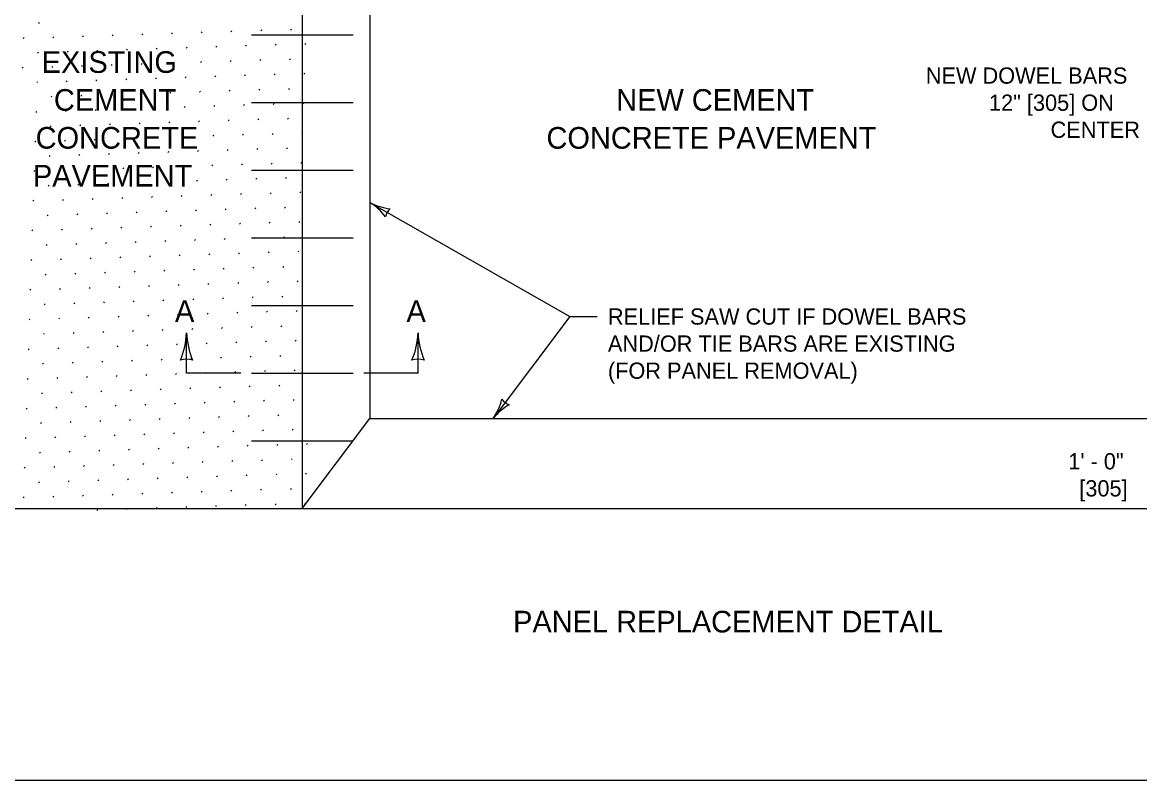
# Model space of a CAD drawing. Extents: x 49991.4 to 50021, y 49987.6 to 50011.4.
# Drawn here: x 50001.323 to 50005.45, y 49987.799 to 49990.601 of the extents above; entities that cross this region are included whole.
import ezdxf

# ---------------------------------------------------------------- set-up
doc = ezdxf.new("R2010")
doc.units = 0
for name, color, linetype in [('Level 1', 7, 'Continuous'), ('Level 10', 7, 'Continuous'), ('Level 2', 7, 'Continuous'), ('Level 3', 7, 'Continuous'), ('Level 4', 7, 'Continuous'), ('Level 6', 7, 'Continuous')]:
    doc.layers.add(name, color=color, linetype=linetype)

msp = doc.modelspace()

# ---------------------------------------------------------------- linework, layer by layer
at = {"layer": 'Level 1'}
for p, q in [((50002.3571, 49991.8039), (50002.3571, 49988.8039)), ((50002.6071, 49991.4706), (50002.6071, 49989.1372)), ((50002.3571, 49988.8039), (50002.6071, 49989.1372)), ((50002.6071, 49989.1372), (50005.8571, 49989.1372)), ((50001.1571, 49988.8039), (50002.3571, 49988.8039)), ((50002.3571, 49988.8039), (50006.1071, 49988.8039))]:
    msp.add_line(p, q, dxfattribs=at)
msp.add_lwpolyline([(49999.3835, 49998.9992), (50016.7501, 49998.9992), (50016.7501, 49987.7988), (49999.3835, 49987.7988)], close=True, dxfattribs=at)
at = {"layer": 'Level 10'}
for p, q in [((50001.3833, 49990.5971), (50001.3869, 49990.6006)), ((50002.094, 49990.5653), (50002.0975, 49990.5689)), ((50002.2036, 49990.5689), (50002.2072, 49990.5724)), ((50002.3132, 49990.5724), (50002.3168, 49990.5759)), ((50001.3267, 49990.5405), (50001.3303, 49990.5441)), ((50001.4364, 49990.5441), (50001.4399, 49990.5476)), ((50001.546, 49990.5476), (50001.5495, 49990.5511)), ((50001.6556, 49990.5512), (50001.6591, 49990.5547)), ((50001.7652, 49990.5547), (50001.7687, 49990.5582)), ((50001.8748, 49990.5582), (50001.8783, 49990.5618)), ((50001.9844, 49990.5618), (50001.9879, 49990.5653)), ((50001.3798, 49990.4875), (50001.3833, 49990.491)), ((50001.4894, 49990.491), (50001.4929, 49990.4946)), ((50001.599, 49990.4946), (50001.6025, 49990.4981)), ((50001.7086, 49990.4981), (50001.7121, 49990.5017)), ((50001.8182, 49990.5017), (50001.8217, 49990.5052)), ((50001.9278, 49990.5052), (50001.9314, 49990.5087)), ((50002.0374, 49990.5087), (50002.041, 49990.5123)), ((50002.147, 49990.5123), (50002.1506, 49990.5158)), ((50002.2566, 49990.5158), (50002.2602, 49990.5194)), ((50002.3663, 49990.5194), (50002.3698, 49990.5229)), ((50001.652, 49990.4415), (50001.6556, 49990.4451)), ((50001.7616, 49990.4451), (50001.7652, 49990.4486)), ((50001.8712, 49990.4486), (50001.8748, 49990.4522)), ((50001.9809, 49990.4522), (50001.9844, 49990.4557)), ((50002.0905, 49990.4557), (50002.094, 49990.4592)), ((50002.2001, 49990.4593), (50002.2036, 49990.4628)), ((50002.3097, 49990.4628), (50002.3132, 49990.4663)), ((50001.3232, 49990.4309), (50001.3267, 49990.4345)), ((50001.4328, 49990.4345), (50001.4363, 49990.438)), ((50001.5424, 49990.438), (50001.546, 49990.4415)), ((50002.0339, 49990.3991), (50002.0374, 49990.4027)), ((50002.1435, 49990.4027), (50002.147, 49990.4062)), ((50002.2531, 49990.4062), (50002.2566, 49990.4098)), ((50002.3627, 49990.4098), (50002.3662, 49990.4133)), ((50001.3762, 49990.3779), (50001.3798, 49990.3814)), ((50001.4858, 49990.3814), (50001.4894, 49990.385)), ((50001.5955, 49990.385), (50001.599, 49990.3885)), ((50001.7051, 49990.3885), (50001.7086, 49990.392)), ((50001.8147, 49990.3921), (50001.8182, 49990.3956)), ((50001.9243, 49990.3956), (50001.9278, 49990.3991)), ((50001.4293, 49990.3248), (50001.4328, 49990.3284)), ((50001.5389, 49990.3284), (50001.5424, 49990.3319)), ((50001.6485, 49990.3319), (50001.652, 49990.3355)), ((50001.7581, 49990.3355), (50001.7616, 49990.339)), ((50001.8677, 49990.339), (50001.8712, 49990.3426)), ((50001.9773, 49990.3426), (50001.9808, 49990.3461)), ((50002.0869, 49990.3461), (50002.0905, 49990.3496)), ((50002.1965, 49990.3496), (50002.2001, 49990.3532)), ((50002.3061, 49990.3532), (50002.3097, 49990.3567)), ((50001.5919, 49990.2754), (50001.5954, 49990.2789)), ((50001.7015, 49990.2789), (50001.7051, 49990.2824)), ((50001.8111, 49990.2824), (50001.8147, 49990.286)), ((50001.9207, 49990.286), (50001.9243, 49990.2895)), ((50002.0303, 49990.2895), (50002.0339, 49990.2931)), ((50002.14, 49990.2931), (50002.1435, 49990.2966)), ((50002.2496, 49990.2966), (50002.2531, 49990.3002)), ((50002.3592, 49990.3002), (50002.3627, 49990.3037)), ((50001.3727, 49990.2683), (50001.3762, 49990.2718)), ((50001.4823, 49990.2718), (50001.4858, 49990.2754)), ((50002.0834, 49990.2365), (50002.0869, 49990.24)), ((50002.193, 49990.24), (50002.1965, 49990.2436)), ((50002.3026, 49990.2436), (50002.3061, 49990.2471)), ((50001.4257, 49990.2152), (50001.4293, 49990.2188)), ((50001.5353, 49990.2188), (50001.5389, 49990.2223)), ((50001.6449, 49990.2223), (50001.6485, 49990.2259)), ((50001.7546, 49990.2259), (50001.7581, 49990.2294)), ((50001.8642, 49990.2294), (50001.8677, 49990.2329)), ((50001.9738, 49990.233), (50001.9773, 49990.2365)), ((50001.3692, 49990.1587), (50001.3727, 49990.1622)), ((50001.4788, 49990.1622), (50001.4823, 49990.1657)), ((50001.5884, 49990.1658), (50001.5919, 49990.1693)), ((50001.698, 49990.1693), (50001.7015, 49990.1728)), ((50001.8076, 49990.1728), (50001.8111, 49990.1764)), ((50001.9172, 49990.1764), (50001.9207, 49990.1799)), ((50002.0268, 49990.1799), (50002.0303, 49990.1835)), ((50002.1364, 49990.1835), (50002.1399, 49990.187)), ((50002.246, 49990.187), (50002.2496, 49990.1905)), ((50002.3556, 49990.1905), (50002.3592, 49990.1941)), ((50001.6414, 49990.1127), (50001.6449, 49990.1163)), ((50001.751, 49990.1163), (50001.7545, 49990.1198)), ((50001.8606, 49990.1198), (50001.8642, 49990.1233)), ((50001.9702, 49990.1233), (50001.9738, 49990.1269)), ((50002.0798, 49990.1269), (50002.0834, 49990.1304)), ((50002.1894, 49990.1304), (50002.193, 49990.134)), ((50002.2991, 49990.134), (50002.3026, 49990.1375)), ((50001.4222, 49990.1056), (50001.4257, 49990.1092)), ((50001.5318, 49990.1092), (50001.5353, 49990.1127)), ((50002.0233, 49990.0703), (50002.0268, 49990.0738)), ((50002.1329, 49990.0739), (50002.1364, 49990.0774)), ((50002.2425, 49990.0774), (50002.246, 49990.0809)), ((50002.3521, 49990.0809), (50002.3556, 49990.0845)), ((50001.3656, 49990.0491), (50001.3691, 49990.0526)), ((50001.4752, 49990.0526), (50001.4788, 49990.0561)), ((50001.5848, 49990.0561), (50001.5884, 49990.0597)), ((50001.6944, 49990.0597), (50001.698, 49990.0632)), ((50001.804, 49990.0632), (50001.8076, 49990.0668)), ((50001.9137, 49990.0668), (50001.9172, 49990.0703)), ((50001.4186, 49989.996), (50001.4222, 49989.9996)), ((50001.5283, 49989.9996), (50001.5318, 49990.0031)), ((50001.6379, 49990.0031), (50001.6414, 49990.0066)), ((50001.7475, 49990.0067), (50001.751, 49990.0102)), ((50001.8571, 49990.0102), (50001.8606, 49990.0137)), ((50001.9667, 49990.0137), (50001.9702, 49990.0173)), ((50002.0763, 49990.0173), (50002.0798, 49990.0208)), ((50002.1859, 49990.0208), (50002.1894, 49990.0244)), ((50002.2955, 49990.0244), (50002.299, 49990.0279)), ((50001.5813, 49989.9465), (50001.5848, 49989.9501)), ((50001.6909, 49989.9501), (50001.6944, 49989.9536)), ((50001.8005, 49989.9536), (50001.804, 49989.9572)), ((50001.9101, 49989.9572), (50001.9136, 49989.9607)), ((50002.0197, 49989.9607), (50002.0233, 49989.9642)), ((50002.1293, 49989.9642), (50002.1329, 49989.9678)), ((50002.2389, 49989.9678), (50002.2425, 49989.9713)), ((50002.3485, 49989.9713), (50002.3521, 49989.9749)), ((50001.3621, 49989.9394), (50001.3656, 49989.943)), ((50001.4717, 49989.943), (50001.4752, 49989.9465)), ((50001.9631, 49989.9041), (50001.9667, 49989.9077)), ((50002.0728, 49989.9077), (50002.0763, 49989.9112)), ((50002.1824, 49989.9112), (50002.1859, 49989.9147)), ((50002.292, 49989.9148), (50002.2955, 49989.9183)), ((50001.4151, 49989.8864), (50001.4186, 49989.89)), ((50001.5247, 49989.89), (50001.5282, 49989.8935)), ((50001.6343, 49989.8935), (50001.6379, 49989.897)), ((50001.7439, 49989.897), (50001.7475, 49989.9006)), ((50001.8535, 49989.9006), (50001.8571, 49989.9041)), ((50001.3585, 49989.8298), (50001.3621, 49989.8334)), ((50001.4681, 49989.8334), (50001.4717, 49989.8369)), ((50001.5777, 49989.8369), (50001.5813, 49989.8405)), ((50001.6873, 49989.8405), (50001.6909, 49989.844)), ((50001.797, 49989.844), (50001.8005, 49989.8475)), ((50001.9066, 49989.8476), (50001.9101, 49989.8511)), ((50002.0162, 49989.8511), (50002.0197, 49989.8546)), ((50002.1258, 49989.8546), (50002.1293, 49989.8582)), ((50002.2354, 49989.8582), (50002.2389, 49989.8617)), ((50002.345, 49989.8617), (50002.3485, 49989.8653)), ((50001.5212, 49989.7803), (50001.5247, 49989.7839)), ((50001.6308, 49989.7839), (50001.6343, 49989.7874)), ((50001.7404, 49989.7874), (50001.7439, 49989.791)), ((50001.85, 49989.791), (50001.8535, 49989.7945)), ((50001.9596, 49989.7945), (50001.9631, 49989.7981)), ((50002.0692, 49989.7981), (50002.0727, 49989.8016)), ((50002.1788, 49989.8016), (50002.1824, 49989.8051)), ((50002.2884, 49989.8051), (50002.292, 49989.8087)), ((50001.4116, 49989.7768), (50001.4151, 49989.7803)), ((50002.0126, 49989.7415), (50002.0162, 49989.745)), ((50002.1222, 49989.745), (50002.1258, 49989.7486)), ((50002.2318, 49989.7486), (50002.2354, 49989.7521)), ((50002.3415, 49989.7521), (50002.345, 49989.7556)), ((50001.355, 49989.7202), (50001.3585, 49989.7238)), ((50001.4646, 49989.7238), (50001.4681, 49989.7273)), ((50001.5742, 49989.7273), (50001.5777, 49989.7309)), ((50001.6838, 49989.7309), (50001.6873, 49989.7344)), ((50001.7934, 49989.7344), (50001.797, 49989.7379)), ((50001.903, 49989.7379), (50001.9066, 49989.7415)), ((50001.408, 49989.6672), (50001.4115, 49989.6707)), ((50001.5176, 49989.6707), (50001.5212, 49989.6743)), ((50001.6272, 49989.6743), (50001.6308, 49989.6778)), ((50001.7368, 49989.6778), (50001.7404, 49989.6814)), ((50001.8464, 49989.6814), (50001.85, 49989.6849)), ((50001.9561, 49989.6849), (50001.9596, 49989.6884)), ((50002.0657, 49989.6885), (50002.0692, 49989.692)), ((50002.1753, 49989.692), (50002.1788, 49989.6955)), ((50002.2849, 49989.6955), (50002.2884, 49989.6991)), ((50001.5707, 49989.6177), (50001.5742, 49989.6212)), ((50001.6803, 49989.6212), (50001.6838, 49989.6248)), ((50001.7899, 49989.6248), (50001.7934, 49989.6283)), ((50001.8995, 49989.6283), (50001.903, 49989.6319)), ((50002.0091, 49989.6319), (50002.0126, 49989.6354)), ((50002.1187, 49989.6354), (50002.1222, 49989.639)), ((50002.2283, 49989.639), (50002.2318, 49989.6425)), ((50002.3379, 49989.6425), (50002.3415, 49989.646)), ((50001.3514, 49989.6106), (50001.355, 49989.6142)), ((50001.461, 49989.6142), (50001.4646, 49989.6177)), ((50001.9525, 49989.5753), (50001.9561, 49989.5788)), ((50002.0621, 49989.5788), (50002.0657, 49989.5824)), ((50002.1717, 49989.5824), (50002.1753, 49989.5859)), ((50002.2813, 49989.5859), (50002.2849, 49989.5895)), ((50001.4045, 49989.5576), (50001.408, 49989.5611)), ((50001.5141, 49989.5611), (50001.5176, 49989.5647)), ((50001.6237, 49989.5647), (50001.6272, 49989.5682)), ((50001.7333, 49989.5682), (50001.7368, 49989.5718)), ((50001.8429, 49989.5718), (50001.8464, 49989.5753)), ((50002.3344, 49989.5329), (50002.3379, 49989.5364)), ((50001.3479, 49989.501), (50001.3514, 49989.5045)), ((50001.4575, 49989.5046), (50001.461, 49989.5081)), ((50001.5671, 49989.5081), (50001.5706, 49989.5116)), ((50001.6767, 49989.5116), (50001.6803, 49989.5152)), ((50001.7863, 49989.5152), (50001.7899, 49989.5187)), ((50001.8959, 49989.5187), (50001.8995, 49989.5223)), ((50002.0055, 49989.5223), (50002.0091, 49989.5258)), ((50002.1152, 49989.5258), (50002.1187, 49989.5293)), ((50002.2248, 49989.5294), (50002.2283, 49989.5329)), ((50001.5105, 49989.4515), (50001.5141, 49989.4551)), ((50001.6201, 49989.4551), (50001.6237, 49989.4586)), ((50001.7298, 49989.4586), (50001.7333, 49989.4621)), ((50001.8394, 49989.4622), (50001.8429, 49989.4657)), ((50001.949, 49989.4657), (50001.9525, 49989.4692)), ((50002.0586, 49989.4692), (50002.0621, 49989.4728)), ((50002.1682, 49989.4728), (50002.1717, 49989.4763)), ((50002.2778, 49989.4763), (50002.2813, 49989.4799)), ((50001.4009, 49989.448), (50001.4045, 49989.4515)), ((50001.8924, 49989.4091), (50001.8959, 49989.4127)), ((50002.002, 49989.4127), (50002.0055, 49989.4162)), ((50002.1116, 49989.4162), (50002.1151, 49989.4197)), ((50002.2212, 49989.4197), (50002.2248, 49989.4233)), ((50002.3308, 49989.4233), (50002.3344, 49989.4268)), ((50001.3444, 49989.3914), (50001.3479, 49989.3949)), ((50001.454, 49989.3949), (50001.4575, 49989.3985)), ((50001.5636, 49989.3985), (50001.5671, 49989.402)), ((50001.6732, 49989.402), (50001.6767, 49989.4056)), ((50001.7828, 49989.4056), (50001.7863, 49989.4091)), ((50001.3974, 49989.3384), (50001.4009, 49989.3419)), ((50001.507, 49989.3419), (50001.5105, 49989.3454)), ((50001.6166, 49989.3455), (50001.6201, 49989.349)), ((50001.7262, 49989.349), (50001.7297, 49989.3525)), ((50001.8358, 49989.3525), (50001.8394, 49989.3561)), ((50001.9454, 49989.3561), (50001.949, 49989.3596)), ((50002.055, 49989.3596), (50002.0586, 49989.3632)), ((50002.1646, 49989.3632), (50002.1682, 49989.3667)), ((50002.2743, 49989.3667), (50002.2778, 49989.3702)), ((50001.4504, 49989.2853), (50001.454, 49989.2889)), ((50001.56, 49989.2889), (50001.5636, 49989.2924)), ((50001.6696, 49989.2924), (50001.6732, 49989.296)), ((50001.7792, 49989.296), (50001.7828, 49989.2995)), ((50001.8889, 49989.2995), (50001.8924, 49989.303)), ((50001.9985, 49989.3031), (50002.002, 49989.3066)), ((50002.1081, 49989.3066), (50002.1116, 49989.3101)), ((50002.2177, 49989.3101), (50002.2212, 49989.3137)), ((50002.3273, 49989.3137), (50002.3308, 49989.3172)), ((50001.3408, 49989.2818), (50001.3443, 49989.2853)), ((50001.9419, 49989.2465), (50001.9454, 49989.25)), ((50002.0515, 49989.25), (50002.055, 49989.2536)), ((50002.1611, 49989.2536), (50002.1646, 49989.2571)), ((50002.2707, 49989.2571), (50002.2742, 49989.2606)), ((50001.3938, 49989.2288), (50001.3974, 49989.2323)), ((50001.5035, 49989.2323), (50001.507, 49989.2358)), ((50001.6131, 49989.2358), (50001.6166, 49989.2394)), ((50001.7227, 49989.2394), (50001.7262, 49989.2429)), ((50001.8323, 49989.2429), (50001.8358, 49989.2465)), ((50002.3237, 49989.2041), (50002.3273, 49989.2076)), ((50001.3373, 49989.1722), (50001.3408, 49989.1757)), ((50001.4469, 49989.1757), (50001.4504, 49989.1793)), ((50001.5565, 49989.1793), (50001.56, 49989.1828)), ((50001.6661, 49989.1828), (50001.6696, 49989.1864)), ((50001.7757, 49989.1864), (50001.7792, 49989.1899)), ((50001.8853, 49989.1899), (50001.8888, 49989.1934)), ((50001.9949, 49989.1934), (50001.9985, 49989.197)), ((50002.1045, 49989.197), (50002.1081, 49989.2005)), ((50002.2141, 49989.2005), (50002.2177, 49989.2041)), ((50001.4999, 49989.1227), (50001.5034, 49989.1262)), ((50001.6095, 49989.1262), (50001.6131, 49989.1298)), ((50001.7191, 49989.1298), (50001.7227, 49989.1333)), ((50001.8287, 49989.1333), (50001.8323, 49989.1369)), ((50001.9383, 49989.1369), (50001.9419, 49989.1404)), ((50002.048, 49989.1404), (50002.0515, 49989.1439)), ((50002.1576, 49989.144), (50002.1611, 49989.1475)), ((50002.2672, 49989.1475), (50002.2707, 49989.151)), ((50001.3903, 49989.1192), (50001.3938, 49989.1227)), ((50001.8818, 49989.0803), (50001.8853, 49989.0838)), ((50001.9914, 49989.0838), (50001.9949, 49989.0874)), ((50002.101, 49989.0874), (50002.1045, 49989.0909)), ((50002.2106, 49989.0909), (50002.2141, 49989.0945)), ((50002.3202, 49989.0945), (50002.3237, 49989.098)), ((50001.3337, 49989.0626), (50001.3373, 49989.0661)), ((50001.4433, 49989.0661), (50001.4469, 49989.0697)), ((50001.5529, 49989.0697), (50001.5565, 49989.0732)), ((50001.6626, 49989.0732), (50001.6661, 49989.0767)), ((50001.7722, 49989.0767), (50001.7757, 49989.0803)), ((50002.2636, 49989.0379), (50002.2672, 49989.0414)), ((50002.3732, 49989.0414), (50002.3761, 49989.0442)), ((50001.3868, 49989.0095), (50001.3903, 49989.0131)), ((50001.4964, 49989.0131), (50001.4999, 49989.0166)), ((50001.606, 49989.0166), (50001.6095, 49989.0202)), ((50001.7156, 49989.0202), (50001.7191, 49989.0237)), ((50001.8252, 49989.0237), (50001.8287, 49989.0273)), ((50001.9348, 49989.0273), (50001.9383, 49989.0308)), ((50002.0444, 49989.0308), (50002.0479, 49989.0343)), ((50002.154, 49989.0343), (50002.1576, 49989.0379)), ((50001.4398, 49988.9565), (50001.4433, 49988.96)), ((50001.5494, 49988.9601), (50001.5529, 49988.9636)), ((50001.659, 49988.9636), (50001.6625, 49988.9671)), ((50001.7686, 49988.9671), (50001.7722, 49988.9707)), ((50001.8782, 49988.9707), (50001.8818, 49988.9742)), ((50001.9878, 49988.9742), (50001.9914, 49988.9778)), ((50002.0974, 49988.9778), (50002.101, 49988.9813)), ((50002.2071, 49988.9813), (50002.2106, 49988.9848)), ((50002.3167, 49988.9849), (50002.3202, 49988.9884)), ((50001.3302, 49988.953), (50001.3337, 49988.9565)), ((50001.8217, 49988.9141), (50001.8252, 49988.9176)), ((50001.9313, 49988.9177), (50001.9348, 49988.9212)), ((50002.0409, 49988.9212), (50002.0444, 49988.9247)), ((50002.1505, 49988.9247), (50002.154, 49988.9283)), ((50002.2601, 49988.9283), (50002.2636, 49988.9318)), ((50002.3697, 49988.9318), (50002.3732, 49988.9354)), ((50001.3832, 49988.8999), (50001.3868, 49988.9035)), ((50001.4928, 49988.9035), (50001.4964, 49988.907)), ((50001.6024, 49988.907), (50001.606, 49988.9106)), ((50001.712, 49988.9106), (50001.7156, 49988.9141)), ((50002.3131, 49988.8752), (50002.3167, 49988.8788)), ((50001.3266, 49988.8434), (50001.3302, 49988.8469)), ((50001.4362, 49988.8469), (50001.4398, 49988.8504)), ((50001.5459, 49988.8504), (50001.5494, 49988.854)), ((50001.6555, 49988.854), (50001.659, 49988.8575)), ((50001.7651, 49988.8575), (50001.7686, 49988.8611)), ((50001.8747, 49988.8611), (50001.8782, 49988.8646)), ((50001.9843, 49988.8646), (50001.9878, 49988.8682)), ((50002.0939, 49988.8682), (50002.0974, 49988.8717)), ((50002.2035, 49988.8717), (50002.207, 49988.8752)), ((50001.5989, 49988.7974), (50001.6024, 49988.8009)), ((50001.7085, 49988.801), (50001.712, 49988.8045)), ((50001.8181, 49988.8045), (50001.8216, 49988.808)), ((50001.9277, 49988.808), (50001.9313, 49988.8116)), ((50002.0373, 49988.8116), (50002.0409, 49988.8151)), ((50002.1469, 49988.8151), (50002.1505, 49988.8187)), ((50002.2565, 49988.8187), (50002.2601, 49988.8222)), ((50002.3662, 49988.8222), (50002.3697, 49988.8257))]:
    msp.add_line(p, q, dxfattribs=at)
at = {"layer": 'Level 3'}
for p, q in [((50002.6071, 49989.9345), (50003.3458, 49989.5137)), ((50003.3458, 49989.5137), (50003.0623, 49989.1372)), ((50003.3458, 49989.5137), (50003.4458, 49989.5137))]:
    msp.add_line(p, q, dxfattribs=at)
for centre, radius, start, end in [((50002.4892, 49989.746), 0.2223, 37.7881, 57.9716), ((50002.7123, 49990.1424), 0.233, 243.1594, 262.4093), ((50002.7185, 49989.871), 0.0548, 132.4709, 168.1933), ((50001.6334, 49989.4661), 0.2964, 337.456, 357.6395), ((50002.2398, 49989.4692), 0.3107, 182.8273, 202.0772), ((50002.4884, 49989.4661), 0.2964, 337.456, 357.6395), ((50003.0948, 49989.4692), 0.3107, 182.8273, 202.0772), ((50001.9296, 49989.2829), 0.073, 72.1388, 107.8612), ((50002.7846, 49989.2829), 0.073, 72.1388, 107.8612), ((50002.8694, 49989.268), 0.233, 325.8496, 345.0994), ((50003.1394, 49989.2396), 0.0548, 215.1611, 250.8834), ((50003.2342, 49988.9963), 0.2223, 120.4783, 140.6618)]:
    msp.add_arc(centre, radius, start, end, dxfattribs=at)
at = {"layer": 'Level 4'}
for p, q in [((50002.1696, 49990.5539), (50002.5446, 49990.5539)), ((50002.1696, 49990.3039), (50002.5446, 49990.3039)), ((50002.1696, 49990.0539), (50002.5446, 49990.0539)), ((50002.1696, 49989.8039), (50002.5446, 49989.8039)), ((50002.1696, 49989.5539), (50002.5446, 49989.5539)), ((50002.1696, 49989.3039), (50002.5446, 49989.3039)), ((50002.1696, 49989.0539), (50002.5446, 49989.0539))]:
    msp.add_line(p, q, dxfattribs=at)
at = {"layer": 'Level 6'}
for p, q in [((50001.9296, 49989.3039), (50001.9296, 49989.4539)), ((50002.7846, 49989.3039), (50002.7846, 49989.4539)), ((50002.1296, 49989.3039), (50001.9296, 49989.3039)), ((50002.7846, 49989.3039), (50002.5846, 49989.3039))]:
    msp.add_line(p, q, dxfattribs=at)

# ---------------------------------------------------------------- texts
at = {"layer": 'Level 2'}
for s, height, p in [('EXISTING', 0.08, (50001.3949, 49990.4139)), ('NEW DOWEL BARS', 0.06, (50004.6598, 49990.3739)), ('CEMENT', 0.08, (50001.4398, 49990.2739)), ('NEW CEMENT', 0.08, (50003.5165, 49990.2738)), ('12" [305] ON', 0.06, (50004.8932, 49990.2739)), ('CONCRETE', 0.08, (50001.3725, 49990.1339)), ('CONCRETE PAVEMENT', 0.08, (50003.259, 49990.1338)), ('CENTER', 0.06, (50005.1206, 49990.1739)), ('PAVEMENT', 0.08, (50001.3624, 49989.9939)), ('A', 0.08, (50001.887, 49989.4939)), ('A', 0.08, (50002.742, 49989.4939)), ('RELIEF SAW CUT IF DOWEL BARS', 0.06, (50003.4858, 49989.4837)), ('AND/OR TIE BARS ARE EXISTING', 0.06, (50003.4858, 49989.3837)), ('(FOR PANEL REMOVAL)', 0.06, (50003.4858, 49989.2837)), ('1\' - 0"', 0.06, (50005.186, 49988.9489)), ('[305]', 0.06, (50005.2266, 49988.8489)), ('PANEL REPLACEMENT DETAIL', 0.08, (50003.1357, 49988.3463))]:
    msp.add_text(s, height=height, dxfattribs=at).set_placement(p)

doc.saveas('drawing.dxf')
